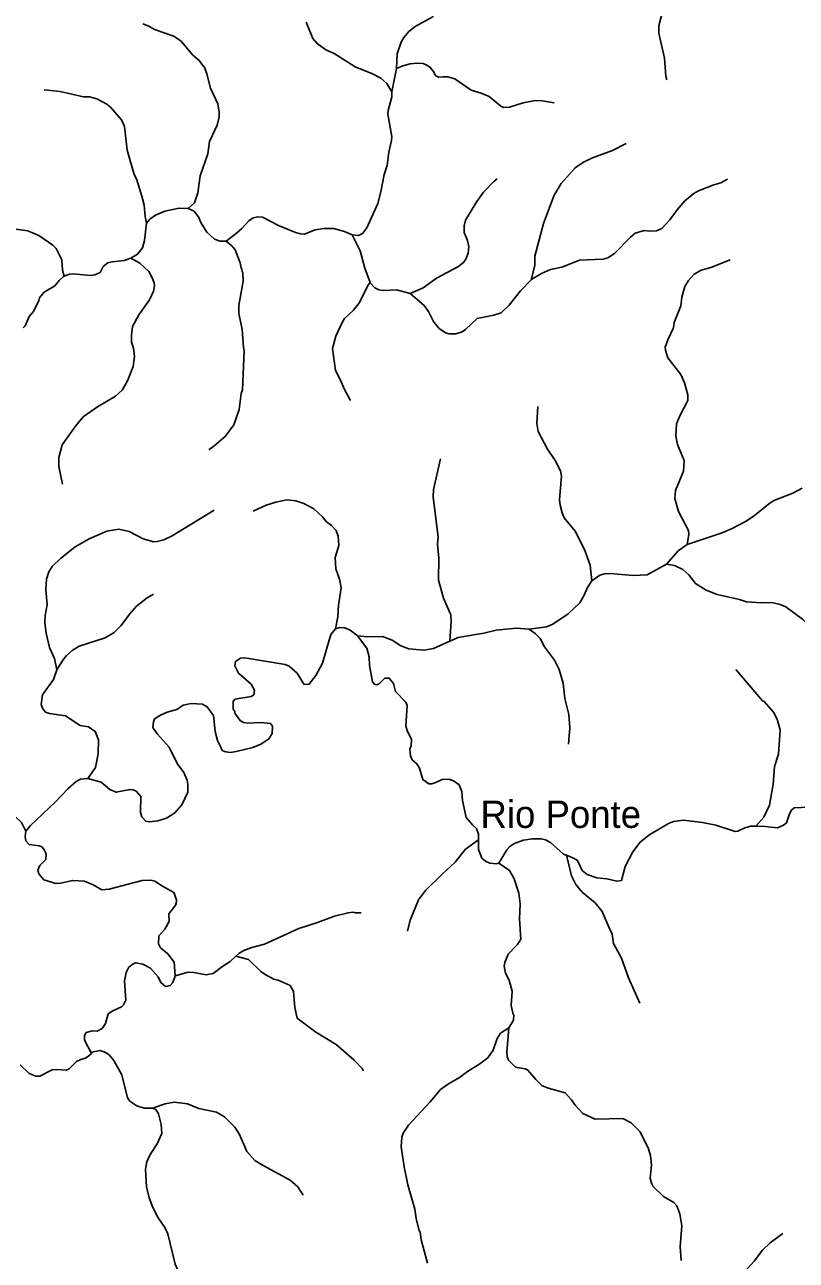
# Model space of a CAD drawing. Extents: x 500 to 555.2, y 9115.7 to 9171.
# Drawn here: x 510.22 to 515.86, y 9143.26 to 9152.3 of the extents above; entities that cross this region are included whole.
import ezdxf
from ezdxf.enums import TextEntityAlignment as Align

# ---------------------------------------------------------------- set-up
doc = ezdxf.new("R2010")
doc.units = 0
doc.header["$LTSCALE"] = 0.064
doc.layers.add('61', color=7, linetype='Continuous')
doc.layers.add('7', color=7, linetype='Continuous', lineweight=25)

msp = doc.modelspace()

# ---------------------------------------------------------------- linework, layer by layer
at = {"layer": '7'}
for points in [[(514.914, 9151.8978), (514.9068, 9151.9238), (514.8968, 9152.0566), (514.8544, 9152.2382), (514.8542, 9152.2928), (514.8725, 9152.3594), (514.905, 9152.4258), (514.9322, 9152.4517), (514.9486, 9152.4765), (514.9674, 9152.5301), (514.9772, 9152.6372), (515.0347, 9152.792), (515.1402, 9153.0228), (515.2342, 9153.1587)], [(513.5793, 9152.7762), (513.4408, 9152.7005), (513.3889, 9152.6569), (513.3655, 9152.6281), (513.2618, 9152.4415), (513.198, 9152.3568), (513.0717, 9152.2871), (513.027, 9152.2506), (512.9891, 9152.2068), (512.9701, 9152.1727), (512.9417, 9152.0866), (512.9372, 9151.9834), (512.9364, 9151.9792)], [(511.0805, 9152.308), (511.1257, 9152.29), (511.1674, 9152.2653), (511.3069, 9152.216), (511.3614, 9152.1808), (511.4448, 9152.0809), (511.4936, 9152.0386), (511.5342, 9151.9816), (511.5503, 9151.9402), (511.5771, 9151.8368), (511.6289, 9151.7206), (511.6391, 9151.6617), (511.6392, 9151.6274), (511.626, 9151.5651), (511.5684, 9151.4455), (511.5566, 9151.3569), (511.4997, 9151.1937), (511.4835, 9151.0704), (511.4596, 9150.9981), (511.4133, 9150.9557)], [(512.2762, 9152.3183), (512.3253, 9152.201), (512.3556, 9152.1625), (512.4201, 9152.1163), (512.4796, 9152.0896), (512.6333, 9151.9916), (512.7618, 9151.9403), (512.8208, 9151.909), (512.8652, 9151.8695), (512.9016, 9151.8105)], [(512.9364, 9151.9792), (512.9271, 9151.9325), (512.9016, 9151.8105)], [(514.0891, 9151.7292), (514.0012, 9151.7438), (513.9509, 9151.7453), (513.862, 9151.7279), (513.7627, 9151.6966), (513.7191, 9151.6948), (513.6985, 9151.7036), (513.6128, 9151.7756), (513.5562, 9151.8009), (513.4815, 9151.8209), (513.3634, 9151.9058), (513.335, 9151.9132), (513.3117, 9151.9193), (513.2771, 9151.92), (513.2463, 9151.9167), (513.2333, 9151.9216), (513.2267, 9151.9247), (513.2184, 9151.934), (513.2053, 9151.961), (513.183, 9151.9879), (513.1582, 9152.0058), (513.1305, 9152.0161), (513.0886, 9152.0194), (513.0367, 9152.0144), (512.9836, 9152.001), (512.9364, 9151.9792)], [(510.3606, 9151.824), (510.4774, 9151.811), (510.648, 9151.7735), (510.6906, 9151.7718), (510.7447, 9151.758), (510.8168, 9151.7186), (510.8444, 9151.6969), (510.9252, 9151.605), (510.9469, 9151.5568), (510.9666, 9151.382), (511.0188, 9151.2057), (511.0341, 9151.174), (511.0749, 9151.0467), (511.0898, 9150.9805), (511.0995, 9150.8971), (511.1078, 9150.8482)], [(512.9016, 9151.8105), (512.9012, 9151.7722), (512.8756, 9151.674), (512.873, 9151.6456), (512.9021, 9151.4836), (512.9005, 9151.4529), (512.8799, 9151.3691), (512.8679, 9151.2705), (512.8463, 9151.2036), (512.8229, 9151.077), (512.801, 9150.9923), (512.7188, 9150.8144), (512.6888, 9150.7724), (512.6582, 9150.7593), (512.6121, 9150.7634)], [(514.6149, 9151.4311), (514.5158, 9151.3794), (514.3698, 9151.3277), (514.3047, 9151.2944), (514.2441, 9151.2533), (514.1407, 9151.1385), (514.0897, 9151.0528), (514.0104, 9150.8463), (513.9472, 9150.6065), (513.9484, 9150.5394), (513.9211, 9150.4349)], [(509.4766, 9151.237), (509.533, 9151.1681), (509.5461, 9151.1353), (509.5514, 9151.0956), (509.5463, 9151.0686), (509.4937, 9150.9706), (509.4907, 9150.9452), (509.4956, 9150.9183), (509.5429, 9150.8031), (509.5498, 9150.8017), (509.6158, 9150.7415), (509.6715, 9150.7221), (509.7086, 9150.7281), (509.8724, 9150.7846), (509.9759, 9150.8056), (510.0816, 9150.8154), (510.2411, 9150.7925), (510.3204, 9150.758), (510.4232, 9150.6879), (510.447, 9150.6624), (510.4889, 9150.579), (510.4933, 9150.5051), (510.5053, 9150.4609)], [(513.6737, 9151.1732), (513.6496, 9151.156), (513.5732, 9151.0745), (513.5226, 9151.0061), (513.4409, 9150.8712), (513.4305, 9150.8297), (513.4306, 9150.78), (513.4551, 9150.7212), (513.4647, 9150.6747), (513.4597, 9150.6296), (513.444, 9150.5854), (513.4271, 9150.56), (513.3838, 9150.5298), (513.2298, 9150.4471), (513.1313, 9150.3756), (513.0368, 9150.333)], [(515.3569, 9151.1695), (515.3075, 9151.1438), (515.2565, 9151.1299), (515.1441, 9151.0849), (515.1096, 9151.066), (515.0449, 9151.0127), (514.9879, 9150.9461), (514.9353, 9150.8719), (514.8779, 9150.81), (514.8389, 9150.7924), (514.7832, 9150.7893), (514.7465, 9150.794), (514.6825, 9150.7746), (514.6466, 9150.7471), (514.5311, 9150.627), (514.4813, 9150.5938), (514.448, 9150.5859), (514.2742, 9150.5774), (514.1456, 9150.5274), (514.063, 9150.5084), (513.9975, 9150.4805), (513.9252, 9150.4381), (513.9211, 9150.4349)], [(511.4133, 9150.9557), (511.3467, 9150.9585), (511.2417, 9150.9366), (511.1729, 9150.9068), (511.1335, 9150.8768), (511.1078, 9150.8482)], [(511.691, 9150.7178), (511.6473, 9150.7178), (511.6051, 9150.7323), (511.55, 9150.7817), (511.5064, 9150.8532), (511.4912, 9150.8898), (511.4555, 9150.9375), (511.4135, 9150.9557), (511.4133, 9150.9557)], [(512.4752, 9150.8098), (512.4063, 9150.8104), (512.3406, 9150.8003), (512.2644, 9150.7682), (512.2331, 9150.7696), (512.197, 9150.7794), (512.0744, 9150.8305), (511.9557, 9150.8934), (511.922, 9150.8941), (511.8886, 9150.8875), (511.8563, 9150.8666), (511.8048, 9150.8089), (511.7655, 9150.7745), (511.691, 9150.7178)], [(511.1078, 9150.8482), (511.0929, 9150.7219), (511.0787, 9150.6689), (511.0419, 9150.621), (510.9936, 9150.5912)], [(512.6121, 9150.7634), (512.5555, 9150.7883), (512.4752, 9150.8098)], [(511.5639, 9149.1902), (511.6008, 9149.2155), (511.686, 9149.2893), (511.7458, 9149.3737), (511.785, 9149.4846), (511.8003, 9149.602), (511.8097, 9149.6285), (511.8229, 9149.9145), (511.8163, 9149.9394), (511.8079, 9150.0706), (511.7837, 9150.1866), (511.7836, 9150.2469), (511.8161, 9150.4252), (511.813, 9150.4858), (511.8068, 9150.4942), (511.8064, 9150.5144), (511.8015, 9150.5179), (511.7931, 9150.5586), (511.7572, 9150.653), (511.7316, 9150.6836), (511.691, 9150.7178)], [(512.7435, 9150.4149), (512.7038, 9150.5185), (512.6695, 9150.6459), (512.6121, 9150.7634)], [(510.493, 9148.9381), (510.4681, 9149.0685), (510.4665, 9149.1335), (510.4909, 9149.2265), (510.5883, 9149.3641), (510.6449, 9149.4306), (510.7497, 9149.5045), (510.8806, 9149.5826), (510.9302, 9149.6274), (510.9697, 9149.6946), (511.0104, 9149.7998), (511.0207, 9149.8734), (511.0128, 9149.9335), (510.9995, 9149.9778), (510.9979, 9150.0297), (511.0062, 9150.0919), (511.051, 9150.1767), (511.1304, 9150.2868), (511.1596, 9150.351), (511.1668, 9150.3872), (511.165, 9150.4109), (511.1506, 9150.4491), (511.1241, 9150.4955), (511.0582, 9150.5553), (510.9936, 9150.5912)], [(510.9936, 9150.5912), (510.9437, 9150.5743), (510.8558, 9150.5661), (510.8257, 9150.5577), (510.79, 9150.5303), (510.7686, 9150.4883), (510.7305, 9150.4694), (510.6968, 9150.4646), (510.5723, 9150.4774), (510.5442, 9150.4761), (510.5053, 9150.4609)], [(515.377, 9150.5798), (515.234, 9150.5243), (515.1653, 9150.5035), (515.113, 9150.4754), (515.0707, 9150.4283), (515.0448, 9150.3858), (515.0234, 9150.3068), (515.015, 9150.2436), (514.9673, 9150.121), (514.9621, 9150.0819), (514.9206, 9149.9956), (514.9019, 9149.9417), (514.903, 9149.9198), (514.9197, 9149.8632), (515.0145, 9149.7416), (515.0433, 9149.6806), (515.0658, 9149.5934), (515.0673, 9149.5498), (515.0077, 9149.4379), (514.9838, 9149.3796), (514.979, 9149.291), (514.9922, 9149.2287), (515.041, 9149.1112), (515.0355, 9149.0338), (514.9775, 9148.892), (514.9723, 9148.8338), (514.998, 9148.7387), (515.0721, 9148.6008), (515.0738, 9148.5732), (515.0624, 9148.4967)], [(510.5053, 9150.4609), (510.5023, 9150.4593), (510.4689, 9150.4293), (510.4389, 9150.3911), (510.3599, 9150.3429), (510.3244, 9150.3029), (510.3214, 9150.2829), (510.2808, 9150.203), (510.2501, 9150.1658), (510.2199, 9150.0972), (510.2054, 9150.0825)], [(513.9211, 9150.4349), (513.8422, 9150.3545), (513.7605, 9150.2484), (513.7026, 9150.1923), (513.6483, 9150.1744), (513.5254, 9150.1517), (513.4413, 9150.0708), (513.4167, 9150.0541), (513.3707, 9150.038), (513.3203, 9150.0379), (513.294, 9150.0457), (513.2488, 9150.0785), (513.2105, 9150.1243), (513.1692, 9150.2015), (513.1384, 9150.2462), (513.0368, 9150.333)], [(512.5995, 9149.5516), (512.5557, 9149.6302), (512.5249, 9149.7049), (512.491, 9149.7693), (512.4676, 9149.9324), (512.492, 9150.0227), (512.5387, 9150.1227), (512.5569, 9150.1502), (512.6213, 9150.2114), (512.6669, 9150.2682), (512.7293, 9150.3967), (512.7435, 9150.4149)], [(513.0368, 9150.333), (512.9365, 9150.3608), (512.8399, 9150.3546), (512.8078, 9150.3609), (512.7775, 9150.3742), (512.7442, 9150.4131), (512.7435, 9150.4149)], [(513.971, 9149.5061), (513.9635, 9149.3816), (513.9717, 9149.325), (514.0399, 9149.1945), (514.0964, 9149.1122), (514.1359, 9149.036), (514.1421, 9148.9984), (514.1293, 9148.8253), (514.1327, 9148.7859), (514.1475, 9148.7293), (514.1634, 9148.6934), (514.242, 9148.594), (514.3114, 9148.4595), (514.3533, 9148.3458), (514.3656, 9148.2304)], [(513.2585, 9149.1243), (513.2071, 9148.8999), (513.2041, 9148.8427), (513.2401, 9148.5541), (513.2353, 9148.4997), (513.245, 9148.3966), (513.2436, 9148.2372), (513.28, 9148.1039), (513.3333, 9147.9832), (513.3369, 9147.9329), (513.3262, 9147.7897)], [(515.9021, 9148.9103), (515.8358, 9148.8736), (515.7033, 9148.8221), (515.6698, 9148.8019), (515.554, 9148.709), (515.4935, 9148.6675), (515.3862, 9148.6126), (515.3615, 9148.6022), (515.3304, 9148.5862), (515.297, 9148.5763), (515.0625, 9148.4968), (515.0624, 9148.4967)], [(511.8871, 9148.7417), (511.9832, 9148.7861), (512.0527, 9148.8077), (512.1352, 9148.8241), (512.199, 9148.8178), (512.2585, 9148.7982), (512.3314, 9148.7585), (512.394, 9148.7007), (512.4236, 9148.6632), (512.4618, 9148.6362), (512.4939, 9148.599), (512.51, 9148.558), (512.5134, 9148.4906), (512.489, 9148.4025), (512.4925, 9148.3202), (512.5186, 9148.2445), (512.5314, 9148.1789), (512.5113, 9148.0539), (512.5069, 9147.9669), (512.4892, 9147.8793)], [(511.6023, 9148.7475), (511.2964, 9148.5601), (511.2342, 9148.5316), (511.1871, 9148.5184), (511.1611, 9148.5174), (511.0837, 9148.5391), (510.9803, 9148.5926), (510.9059, 9148.6092), (510.8185, 9148.5959), (510.6891, 9148.5394), (510.5862, 9148.4796), (510.4785, 9148.395), (510.4183, 9148.3364), (510.3943, 9148.2976), (510.3758, 9148.2427), (510.3713, 9148.1649), (510.3828, 9148.0557), (510.3663, 9147.9788), (510.3649, 9147.923), (510.3746, 9147.8482), (510.3989, 9147.7446), (510.436, 9147.662), (510.4535, 9147.5792)], [(515.0624, 9148.4967), (514.997, 9148.4501), (514.9113, 9148.354)], [(514.9113, 9148.354), (514.9098, 9148.3523), (514.7689, 9148.2764), (514.6672, 9148.2698), (514.496, 9148.2844), (514.4599, 9148.2826), (514.4245, 9148.2728), (514.3656, 9148.2304)], [(516.0734, 9147.8044), (515.9979, 9147.8641), (515.9044, 9147.951), (515.783, 9148.0406), (515.7423, 9148.0579), (515.6809, 9148.0728), (515.6062, 9148.0697), (515.496, 9148.0765), (515.4444, 9148.0956), (515.281, 9148.1313), (515.2008, 9148.1637), (515.1226, 9148.2115), (515.073, 9148.2756), (515.0297, 9148.3139), (514.9702, 9148.3447), (514.9113, 9148.354)], [(514.3656, 9148.2304), (514.3652, 9148.2301), (514.3329, 9148.1831), (514.3098, 9148.1276), (514.2759, 9148.0693), (514.1926, 9147.9888), (514.0786, 9147.9131), (514.0338, 9147.895), (513.9057, 9147.8773)], [(511.1593, 9148.1349), (511.1132, 9148.1059), (511.0357, 9148.0449), (510.9833, 9147.9883), (510.9232, 9147.9048), (510.8708, 9147.8521), (510.8056, 9147.8136), (510.6148, 9147.7539), (510.5653, 9147.7223), (510.5238, 9147.684), (510.4959, 9147.6497), (510.4535, 9147.5792)], [(512.4892, 9147.8793), (512.4557, 9147.8386), (512.3943, 9147.6297), (512.347, 9147.5385), (512.2945, 9147.4727), (512.258, 9147.4761), (512.2092, 9147.5549), (512.1521, 9147.6072), (512.1214, 9147.6184), (511.8269, 9147.6676), (511.7957, 9147.6655)], [(512.6503, 9147.8292), (512.6489, 9147.8311), (512.5984, 9147.8708), (512.5586, 9147.8879), (512.5223, 9147.8894), (512.4892, 9147.8793)], [(513.1358, 9147.7235), (513.0264, 9147.7341), (512.9679, 9147.7564), (512.9049, 9147.7976), (512.8333, 9147.8234), (512.7244, 9147.8219), (512.6503, 9147.8292)], [(513.5364, 9146.3351), (513.537, 9146.3773), (513.522, 9146.4194), (513.491, 9146.4462), (513.4467, 9146.4989), (513.4191, 9146.6239), (513.414, 9146.6895), (513.3958, 9146.7375), (513.3531, 9146.768), (513.3189, 9146.7803), (513.2702, 9146.7771), (513.2251, 9146.7546), (513.1936, 9146.7459), (513.173, 9146.7466), (513.1288, 9146.7772), (513.104, 9146.8607), (513.0852, 9146.8923), (513.0514, 9146.922), (513.0385, 9146.9516), (513.0356, 9146.9718), (513.0336, 9147.001), (513.0438, 9147.0229), (513.0465, 9147.0699), (513.0155, 9147.1363), (513.0056, 9147.1698), (513.0138, 9147.32), (513.0055, 9147.3445), (512.9292, 9147.421), (512.915, 9147.4808), (512.8827, 9147.5179), (512.8499, 9147.5182), (512.8129, 9147.4792), (512.792, 9147.4712), (512.7761, 9147.476), (512.76, 9147.4921), (512.7383, 9147.6126), (512.7365, 9147.675), (512.7187, 9147.7392), (512.6503, 9147.8292)], [(513.9057, 9147.8773), (513.8116, 9147.8859), (513.6648, 9147.8697), (513.5762, 9147.8484), (513.3872, 9147.817), (513.3262, 9147.7897)], [(514.1939, 9147.0369), (514.2028, 9147.1546), (514.1965, 9147.2537), (514.1669, 9147.3698), (514.154, 9147.4828), (514.126, 9147.5819), (514.0911, 9147.6519), (514.0188, 9147.7481), (513.9861, 9147.8092), (513.9536, 9147.8432), (513.9057, 9147.8773)], [(513.3262, 9147.7897), (513.208, 9147.7368), (513.1358, 9147.7235)], [(511.7957, 9147.6655), (511.7579, 9147.6416), (511.7542, 9147.6092), (511.7803, 9147.5564), (511.8725, 9147.4751), (511.8982, 9147.4324), (511.8937, 9147.3982), (511.8737, 9147.3841), (511.7552, 9147.3651), (511.7426, 9147.3471), (511.7428, 9147.2891), (511.7505, 9147.2821), (511.7568, 9147.258), (511.7947, 9147.2073), (511.8179, 9147.195), (511.8497, 9147.1888), (511.941, 9147.1953), (512.0147, 9147.1869), (512.0292, 9147.1689), (512.0263, 9147.1141), (512.0027, 9147.0751), (511.943, 9147.0356), (511.8846, 9147.0113), (511.7644, 9146.9834), (511.7218, 9146.9747), (511.6873, 9146.979), (511.6611, 9146.9892), (511.6485, 9147.0185), (511.6273, 9147.0623), (511.6111, 9147.1279), (511.598, 9147.246), (511.5515, 9147.3089), (511.5186, 9147.3282), (511.4358, 9147.333), (511.3764, 9147.3215), (511.334, 9147.2933), (511.3022, 9147.2815), (511.2603, 9147.2705), (511.2113, 9147.2487), (511.1673, 9147.2203), (511.1584, 9147.2005), (511.1544, 9147.1581), (511.1869, 9147.1128), (511.275, 9147.0149), (511.3322, 9146.8942), (511.3823, 9146.8299), (511.4058, 9146.7735), (511.4111, 9146.7433), (511.4093, 9146.6837), (511.3659, 9146.5924), (511.3144, 9146.5327), (511.2554, 9146.495), (511.1915, 9146.4749), (511.1289, 9146.4671), (511.1025, 9146.4723), (511.0751, 9146.5032), (511.0654, 9146.5353), (511.0665, 9146.6523), (511.0322, 9146.6932), (511.0116, 9146.7029), (510.9864, 9146.7032), (510.8873, 9146.6838), (510.8388, 9146.7049), (510.7762, 9146.7587), (510.6794, 9146.7859)], [(510.4535, 9147.5792), (510.4282, 9147.5097), (510.347, 9147.3976), (510.3372, 9147.3259), (510.35, 9147.2954), (510.3698, 9147.2709), (510.3982, 9147.2593), (510.5167, 9147.2429), (510.6223, 9147.1732), (510.6846, 9147.1623), (510.7327, 9147.1299), (510.7567, 9147.0668), (510.7534, 9146.9657), (510.7352, 9146.8642), (510.6794, 9146.7859)], [(515.4171, 9147.582), (515.6123, 9147.3541), (515.6254, 9147.3488), (515.694, 9147.2707), (515.7196, 9147.2201), (515.7432, 9147.1384), (515.73, 9146.9625), (515.7005, 9146.8732), (515.6907, 9146.7426), (515.6629, 9146.5891), (515.6217, 9146.5022), (515.5642, 9146.4352)], [(509.1587, 9147.1846), (509.3231, 9147.0624), (509.4324, 9146.9531), (509.4915, 9146.907), (509.5483, 9146.8935), (509.6718, 9146.8985), (509.7064, 9146.8919), (509.751, 9146.8575), (509.818, 9146.7564), (509.8567, 9146.7127), (510.0007, 9146.5983), (510.0443, 9146.5785), (510.146, 9146.5085), (510.1938, 9146.462), (510.2253, 9146.3998)], [(510.6794, 9146.7859), (510.6249, 9146.7788), (510.5948, 9146.7629), (510.5321, 9146.7097), (510.4422, 9146.6135), (510.2566, 9146.4389), (510.2253, 9146.3998)], [(516.2597, 9146.4872), (516.2241, 9146.5133), (516.1664, 9146.5522), (516.1002, 9146.572), (516.0018, 9146.5785), (515.8451, 9146.5701), (515.8261, 9146.5527), (515.811, 9146.5272), (515.7885, 9146.4601), (515.7672, 9146.4438), (515.722, 9146.4244), (515.6317, 9146.4342), (515.5642, 9146.4352)], [(515.5642, 9146.4352), (515.5265, 9146.4358), (515.4847, 9146.4245), (515.4321, 9146.3984), (515.4125, 9146.3982), (515.2708, 9146.4424), (515.1731, 9146.4636), (515.0353, 9146.4801), (514.9631, 9146.4703), (514.9264, 9146.4555), (514.7821, 9146.3702), (514.7193, 9146.3189), (514.6644, 9146.2494), (514.6083, 9146.1415), (514.5829, 9146.0393), (514.5487, 9146.0327), (514.4743, 9146.0502), (514.4008, 9146.0571), (514.33, 9146.0813), (514.2929, 9146.1117), (514.2589, 9146.1859), (514.2313, 9146.2027), (514.1789, 9146.224)], [(510.2253, 9146.3998), (510.2197, 9146.3615), (510.2255, 9146.3279), (510.2489, 9146.3029), (510.3255, 9146.2933), (510.3422, 9146.2855), (510.3581, 9146.2669), (510.3743, 9146.2341), (510.3709, 9146.1933), (510.3288, 9146.1472), (510.3139, 9146.1148), (510.3202, 9146.0871), (510.3582, 9146.0442), (510.4458, 9146.0176), (510.4786, 9146.0194), (510.5683, 9146.0388), (510.6558, 9146.0328), (510.7174, 9146.0077), (510.7812, 9145.9701), (510.8362, 9145.9751), (511.0776, 9146.0387), (511.1388, 9146.0403), (511.1692, 9146.0343), (511.2248, 9145.9959), (511.308, 9145.9512), (511.3273, 9145.8969), (511.3242, 9145.8675), (511.3157, 9145.8505), (511.2719, 9145.7938), (511.2748, 9145.7388), (511.2411, 9145.6834), (511.1988, 9145.6346)], [(513.0159, 9145.6667), (513.0352, 9145.7486), (513.0982, 9145.8973), (513.1479, 9145.9662), (513.2692, 9146.086), (513.3665, 9146.1734), (513.4415, 9146.2681), (513.5364, 9146.3351)], [(513.685, 9146.165), (513.6643, 9146.16), (513.62, 9146.1649), (513.588, 9146.18), (513.5594, 9146.2022), (513.5354, 9146.2643), (513.5364, 9146.3351)], [(514.1789, 9146.224), (514.1583, 9146.2324), (514.0634, 9146.3176), (514.0249, 9146.3354), (513.9941, 9146.3424), (513.9305, 9146.3441), (513.8641, 9146.3342), (513.7993, 9146.3102), (513.7672, 9146.2886), (513.7438, 9146.2636), (513.685, 9146.165)], [(514.7157, 9145.1412), (514.6323, 9145.3265), (514.5815, 9145.4702), (514.5231, 9145.5765), (514.5145, 9145.6468), (514.4904, 9145.6923), (514.4404, 9145.8114), (514.3883, 9145.8748), (514.2953, 9145.953), (514.2469, 9146.0084), (514.2164, 9146.0727), (514.1789, 9146.224)], [(513.7908, 9145.0164), (513.7945, 9145.0552), (513.7898, 9145.0587), (513.7749, 9145.1227), (513.783, 9145.2296), (513.7604, 9145.3084), (513.7323, 9145.3616), (513.7241, 9145.4133), (513.7289, 9145.4396), (513.7529, 9145.4994), (513.8202, 9145.571), (513.8452, 9145.6093), (513.8356, 9145.757), (513.8404, 9145.8667), (513.8303, 9145.9468), (513.7975, 9146.051), (513.7615, 9146.111), (513.685, 9146.165)], [(512.6785, 9145.802), (512.637, 9145.802), (512.6202, 9145.8074), (512.5825, 9145.803), (512.4824, 9145.7779), (512.3582, 9145.7302), (512.2221, 9145.6875), (511.9714, 9145.573), (511.8794, 9145.5486), (511.821, 9145.5259), (511.7841, 9145.505), (511.7611, 9145.4836)], [(511.1988, 9145.6346), (511.1965, 9145.5748), (511.2106, 9145.5461), (511.2643, 9145.5016), (511.3113, 9145.4405), (511.3165, 9145.3421)], [(511.7611, 9145.4836), (511.7197, 9145.4452), (511.6655, 9145.4123), (511.5953, 9145.3578), (511.5435, 9145.3485), (511.4537, 9145.3662), (511.4133, 9145.368), (511.3165, 9145.3421)], [(512.6944, 9144.6448), (512.6863, 9144.6618), (512.6274, 9144.7226), (512.4963, 9144.8375), (512.3466, 9144.9297), (512.2111, 9145.0308), (512.1936, 9145.1096), (512.182, 9145.227), (512.1578, 9145.2706), (512.0704, 9145.3083), (512.0381, 9145.3162), (511.976, 9145.3497), (511.9444, 9145.373), (511.8548, 9145.4601), (511.7611, 9145.4836)], [(511.3165, 9145.3421), (511.2995, 9145.291), (511.2815, 9145.2699), (511.2476, 9145.2639), (511.2141, 9145.2916), (511.1926, 9145.3325), (511.1384, 9145.398), (511.0815, 9145.427), (511.0307, 9145.4368), (511.0094, 9145.4286), (510.9791, 9145.4043), (510.9598, 9145.3665), (510.9474, 9145.3039), (510.9568, 9145.1629), (510.94, 9145.1281), (510.9249, 9145.113), (510.8612, 9145.0838), (510.8289, 9145.062), (510.8077, 9144.9914), (510.7829, 9144.9549), (510.7475, 9144.9355), (510.7141, 9144.9381), (510.6674, 9144.9256), (510.6537, 9144.9036), (510.655, 9144.871), (510.7061, 9144.7725)], [(513.1631, 9143.2389), (513.1172, 9143.4096), (513.1089, 9143.4661), (513.1027, 9143.4748), (513.0797, 9143.5658), (513.071, 9143.6332), (513.0204, 9143.8114), (512.9928, 9143.9422), (512.9696, 9144.0907), (512.975, 9144.1595), (512.9841, 9144.1897), (513.0237, 9144.2493), (513.1828, 9144.4183), (513.2577, 9144.5081), (513.3173, 9144.5511), (513.3962, 9144.5966), (513.4561, 9144.6411), (513.5466, 9144.6958), (513.6031, 9144.7402), (513.6439, 9144.7978), (513.6732, 9144.8825), (513.6971, 9144.9206), (513.7574, 9144.9596), (513.7908, 9145.0164)], [(515.0182, 9143.2586), (515.0102, 9143.3585), (515.0231, 9143.5112), (515.0083, 9143.5998), (514.9869, 9143.6588), (514.9644, 9143.683), (514.8878, 9143.7264), (514.8108, 9143.8007), (514.8096, 9143.8112), (514.8033, 9143.8153), (514.7903, 9143.8605), (514.8016, 9143.9574), (514.7946, 9144.0256), (514.7769, 9144.0826), (514.717, 9144.2013), (514.6535, 9144.2645), (514.5917, 9144.2968), (514.3894, 9144.292), (514.2997, 9144.3336), (514.2418, 9144.3942), (514.2172, 9144.4336), (514.17, 9144.4837), (514.0446, 9144.5182), (514.0002, 9144.5379), (513.9548, 9144.5812), (513.8957, 9144.6499), (513.8776, 9144.661), (513.8072, 9144.673), (513.7555, 9144.7247), (513.7456, 9144.7507), (513.7438, 9144.7823), (513.7574, 9144.9596)], [(510.7061, 9144.7725), (510.6858, 9144.7551), (510.6627, 9144.7378), (510.6282, 9144.7296), (510.5961, 9144.7151), (510.5416, 9144.6596), (510.5195, 9144.6509), (510.4523, 9144.6561), (510.4189, 9144.6527), (510.3288, 9144.607), (510.2993, 9144.6074), (510.25, 9144.627), (510.1832, 9144.6902)], [(511.1526, 9144.3716), (511.1511, 9144.3721), (511.0916, 9144.3737), (511.0363, 9144.3887), (510.9869, 9144.4229), (510.9701, 9144.4483), (510.9277, 9144.6154), (510.8681, 9144.7212), (510.8353, 9144.7625), (510.8091, 9144.7792), (510.77, 9144.7937), (510.7063, 9144.7827), (510.7061, 9144.7725)], [(511.3674, 9143.1222), (511.3166, 9143.231), (511.2652, 9143.4522), (511.2419, 9143.4987), (511.1927, 9143.5708), (511.1556, 9143.6452), (511.1279, 9143.7166), (511.1078, 9143.7966), (511.0996, 9143.9272), (511.1094, 9143.9797), (511.1347, 9144.0341), (511.1861, 9144.1123), (511.2208, 9144.1873), (511.2157, 9144.254), (511.1949, 9144.3308), (511.1758, 9144.3635), (511.1526, 9144.3716)], [(512.2527, 9143.7351), (512.2137, 9143.7961), (512.1582, 9143.8449), (511.9602, 9143.9531), (511.8991, 9143.9908), (511.8424, 9144.0563), (511.7883, 9144.1809), (511.7544, 9144.2325), (511.6792, 9144.3081), (511.6373, 9144.3327), (511.6195, 9144.3427), (511.491, 9144.3695), (511.409, 9144.4036), (511.3105, 9144.4165), (511.2455, 9144.4052), (511.1526, 9144.3716)], [(515.7605, 9143.4566), (515.6682, 9143.3868), (515.6139, 9143.3328), (515.5521, 9143.2529), (515.4282, 9143.116), (515.3856, 9143.0815), (515.2817, 9143.0149), (515.2586, 9142.9905)]]:
    msp.add_lwpolyline(points, dxfattribs=at)

# ---------------------------------------------------------------- texts
at = {"layer": '61'}
msp.add_text('Rio Ponte', height=0.2, dxfattribs=at).set_placement((514.1377, 9146.4232), align=Align.CENTER)

doc.saveas('drawing.dxf')
